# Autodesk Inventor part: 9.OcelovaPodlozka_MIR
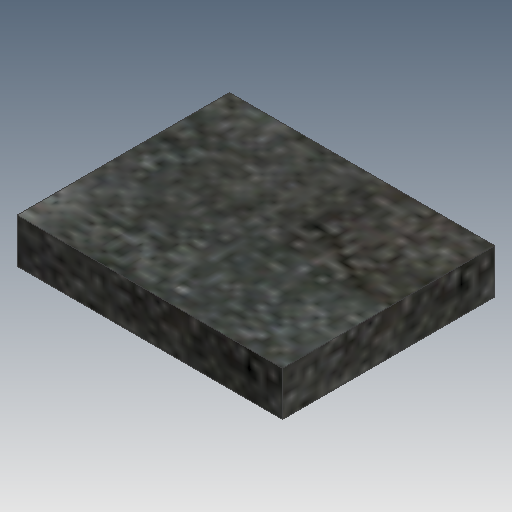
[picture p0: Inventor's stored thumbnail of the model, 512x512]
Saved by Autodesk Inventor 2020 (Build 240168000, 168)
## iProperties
Created: 2022-02
Part Number: 9.OcelovaPodlozka_MIR
Material: Steel
Document SubType Name: Modeling
Designer: marti
Mass: 28.26 g
Surface Area: 19.8 cm^2
Volume: 3.6 cm^3
Density: 7.85 g/cm^3
Appearance: Plate
Author: marti
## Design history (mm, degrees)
derived "9.OcelovaPodlozka.ipt"
  sketch "Sketch1"
    geometry: L1 (-15, 12)-(15, 12) reference; L2 (15, 12)-(15, -12) reference; L3 (15, -12)-(-15, -12) reference; L4 (-15, -12)-(-15, 12) reference; L5 (-15, 12)-(15, -12) reference; L6 (15, 12)-(-15, -12) reference; 1 further point
    dimensions: "d0" = 10 dimension on point (0, 0) L1.start L2.end L1.end L3.end L1 L2 L3 L4 L5 L6
feature "Solid1::9.OcelovaPodlozka.ipt" dims "d0" = 10
tag "TaggingFeature1"
body "Solid1"
